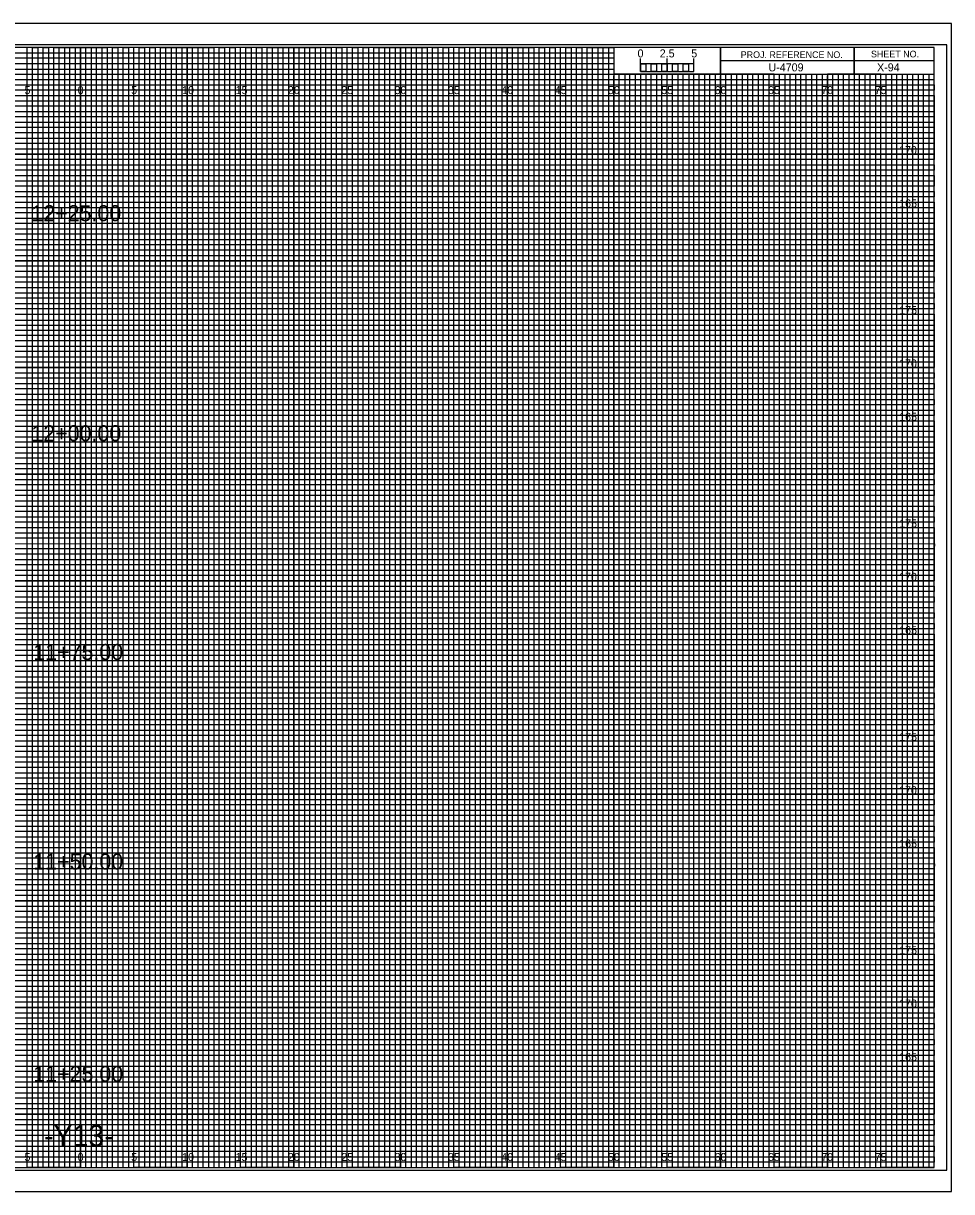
# Model space of a CAD drawing. Extents: x -7 to 162, y 108 to 217.
# Drawn here: x 74.6 to 161.7, y 107.7 to 217.2 of the extents above; entities that cross this region are included whole.
import ezdxf

# ---------------------------------------------------------------- set-up
doc = ezdxf.new("R2010")
doc.units = 0
for name, color, linetype in [('Exist Cross Section Cell', 7, 'Continuous'), ('Exist XS Center Line Elevation Label', 7, 'Continuous'), ('Exist XS Ground Line', 7, 'Continuous'), ('Prop CMT Conc Surface', 7, 'Continuous'), ('Prop CMT Concrete Structures', 7, 'Continuous'), ('Prop CMT Pvmt Course 1', 7, 'Continuous'), ('Prop CMT Pvmt Course 1 CG', 7, 'Continuous'), ('Prop CMT Pvmt Course 2', 7, 'Continuous'), ('Prop CMT Pvmt Course 3', 7, 'Continuous'), ('Prop CMT Pvmt Surface', 7, 'Continuous'), ('Prop CMT Slope Grass', 7, 'Continuous'), ('Prop CMT Subgrade Earthwork', 7, 'Continuous'), ('Prop XS Finish Grade CurbGutter', 7, 'Continuous'), ('Prop XS Hydro Elevations', 7, 'Continuous'), ('Prop XS SE Text', 7, 'Continuous'), ('Prop XS Side Slope Text', 7, 'Continuous'), ('Scratch_Level_0', 7, 'Continuous')]:
    doc.layers.add(name, color=color, linetype=linetype)

msp = doc.modelspace()

# ---------------------------------------------------------------- linework, layer by layer
at = {"layer": 'Exist XS Center Line Elevation Label'}
for points in [[(72.5, 110), (77.5, 110), (77.5, 215), (82.5, 215), (82.5, 110), (87.5, 110), (87.5, 215), (92.5, 215), (92.5, 110), (97.5, 110), (97.5, 215), (102.5, 215), (102.5, 110), (107.5, 110), (107.5, 215), (112.5, 215), (112.5, 110), (117.5, 110), (117.5, 215), (122.5, 215), (122.5, 110), (127.5, 110), (127.5, 215), (129.97, 215), (130, 215), (130, 212.5), (132.5, 212.5), (132.5, 110), (137.5, 110), (137.5, 212.5), (142.5, 212.5), (142.5, 110), (147.5, 110), (147.5, 212.5), (152.5, 212.5), (152.5, 110), (157.5, 110), (157.5, 212.5)], [(0, 212.5), (137.5, 212.5)], [(0, 202.5), (160, 202.5), (160, 207.5), (0, 207.5)], [(0, 192.5), (160, 192.5), (160, 197.5), (0, 197.5)], [(0, 182.5), (160, 182.5), (160, 187.5), (0, 187.5)], [(0, 172.5), (160, 172.5), (160, 177.5), (0, 177.5)], [(0, 162.5), (160, 162.5), (160, 167.5), (0, 167.5)], [(0, 152.5), (160, 152.5), (160, 157.5), (0, 157.5)], [(0, 142.5), (160, 142.5), (160, 147.5), (0, 147.5)], [(0, 132.5), (160, 132.5), (160, 137.5), (0, 137.5)], [(0, 122.5), (160, 122.5), (160, 127.5), (0, 127.5)], [(0, 112.5), (160, 112.5), (160, 117.5), (0, 117.5)]]:
    msp.add_lwpolyline(points, dxfattribs=at)
at = {"layer": 'Exist XS Ground Line'}
for p, q in [((75, 215), (70, 215)), ((75, 110), (75, 215)), ((85, 215), (80, 215)), ((80, 215), (80, 110)), ((85, 110), (85, 215)), ((95, 215), (90, 215)), ((90, 215), (90, 110)), ((95, 110), (95, 215)), ((105, 215), (100, 215)), ((100, 215), (100, 110)), ((105, 110), (105, 215)), ((115, 215), (110, 215)), ((110, 215), (110, 110)), ((115, 110), (115, 215)), ((125, 215), (120, 215)), ((120, 215), (120, 110)), ((125, 110), (125, 215)), ((130, 215), (130, 110)), ((135, 110), (135, 212.5)), ((145, 212.5), (140, 212.5)), ((140, 212.5), (140, 110)), ((145, 110), (145, 212.5)), ((155, 212.5), (150, 212.5)), ((150, 212.5), (150, 110)), ((155, 110), (155, 212.5)), ((80, 110), (75, 110)), ((90, 110), (85, 110)), ((100, 110), (95, 110)), ((110, 110), (105, 110)), ((120, 110), (115, 110)), ((130, 110), (125, 110)), ((140, 110), (135, 110)), ((150, 110), (145, 110)), ((160, 110), (155, 110)), ((160, 110), (160, 110))]:
    msp.add_line(p, q, dxfattribs=at)
for points in [[(0, 210), (160, 210), (160, 205), (0, 205)], [(0, 200), (160, 200), (160, 195), (0, 195)], [(0, 190), (160, 190), (160, 185), (0, 185)], [(0, 180), (160, 180), (160, 175), (0, 175)], [(0, 170), (160, 170), (160, 165), (0, 165)], [(0, 160), (160, 160), (160, 155), (0, 155)], [(0, 150), (160, 150), (160, 145), (0, 145)], [(0, 140), (160, 140), (160, 135), (0, 135)], [(0, 130), (160, 130), (160, 125), (0, 125)], [(0, 120), (160, 120), (160, 115), (0, 115)]]:
    msp.add_lwpolyline(points, dxfattribs=at)
at = {"layer": 'Prop CMT Conc Surface'}
for p, q in [((75, 110), (75, 215)), ((80, 110), (80, 215)), ((85, 110), (85, 215)), ((90, 110), (90, 215)), ((95, 110), (95, 215)), ((100, 110), (100, 215)), ((105, 110), (105, 215)), ((110, 110), (110, 215)), ((115, 110), (115, 215)), ((120, 110), (120, 215)), ((125, 110), (125, 215)), ((130, 110), (130, 212.34)), ((135, 110), (135, 212.34)), ((140, 110), (140, 212.34)), ((145, 110), (145, 212.34)), ((150, 110), (150, 212.34)), ((155, 110), (155, 212.34)), ((0, 210), (160, 210)), ((0, 205), (160, 205)), ((0, 200), (160, 200)), ((0, 195), (160, 195)), ((0, 190), (160, 190)), ((0, 185), (160, 185)), ((0, 180), (160, 180)), ((0, 175), (160, 175)), ((0, 170), (160, 170)), ((0, 165), (160, 165)), ((0, 160), (160, 160)), ((0, 155), (160, 155)), ((0, 150), (160, 150)), ((0, 145), (160, 145)), ((0, 140), (160, 140)), ((0, 135), (160, 135)), ((0, 130), (160, 130)), ((0, 125), (160, 125)), ((0, 120), (160, 120)), ((0, 115), (160, 115))]:
    msp.add_line(p, q, dxfattribs=at)
at = {"layer": 'Prop CMT Pvmt Course 1'}
for p, q in [((133.5, 212.5), (133, 212.5)), ((133, 212.5), (133, 110)), ((133.5, 110), (133.5, 212.5)), ((134.5, 212.5), (134, 212.5)), ((134, 212.5), (134, 110)), ((134.5, 110), (134.5, 212.5)), ((133, 110), (132.5, 110)), ((134, 110), (133.5, 110))]:
    msp.add_line(p, q, dxfattribs=at)
for points in [[(75, 110), (75.5, 110), (75.5, 215), (76, 215), (76, 110)], [(76, 110), (76.5, 110), (76.5, 215), (77, 215), (77, 110)], [(77.5, 110), (78, 110), (78, 215), (78.5, 215), (78.5, 110)], [(78.5, 110), (79, 110), (79, 215), (79.5, 215), (79.5, 110)], [(80, 110), (80.5, 110), (80.5, 215), (81, 215), (81, 110)], [(81, 110), (81.5, 110), (81.5, 215), (82, 215), (82, 110)], [(82.5, 110), (83, 110), (83, 215), (83.5, 215), (83.5, 110)], [(83.5, 110), (84, 110), (84, 215), (84.5, 215), (84.5, 110)], [(85, 110), (85.5, 110), (85.5, 215), (86, 215), (86, 110)], [(86, 110), (86.5, 110), (86.5, 215), (87, 215), (87, 110)], [(87.5, 110), (88, 110), (88, 215), (88.5, 215), (88.5, 110)], [(88.5, 110), (89, 110), (89, 215), (89.5, 215), (89.5, 110)], [(90, 110), (90.5, 110), (90.5, 215), (91, 215), (91, 110)], [(91, 110), (91.5, 110), (91.5, 215), (92, 215), (92, 110)], [(92.5, 110), (93, 110), (93, 215), (93.5, 215), (93.5, 110)], [(93.5, 110), (94, 110), (94, 215), (94.5, 215), (94.5, 110)], [(95, 110), (95.5, 110), (95.5, 215), (96, 215), (96, 110)], [(96, 110), (96.5, 110), (96.5, 215), (97, 215), (97, 110)], [(97.5, 110), (98, 110), (98, 215), (98.5, 215), (98.5, 110)], [(98.5, 110), (99, 110), (99, 215), (99.5, 215), (99.5, 110)], [(100, 110), (100.5, 110), (100.5, 215), (101, 215), (101, 110)], [(101, 110), (101.5, 110), (101.5, 215), (102, 215), (102, 110)], [(102.5, 110), (103, 110), (103, 215), (103.5, 215), (103.5, 110)], [(103.5, 110), (104, 110), (104, 215), (104.5, 215), (104.5, 110)], [(105, 110), (105.5, 110), (105.5, 215), (106, 215), (106, 110)], [(106, 110), (106.5, 110), (106.5, 215), (107, 215), (107, 110)], [(107.5, 110), (108, 110), (108, 215), (108.5, 215), (108.5, 110)], [(108.5, 110), (109, 110), (109, 215), (109.5, 215), (109.5, 110)], [(110, 110), (110.5, 110), (110.5, 215), (111, 215), (111, 110)], [(111, 110), (111.5, 110), (111.5, 215), (112, 215), (112, 110)], [(112.5, 110), (113, 110), (113, 215), (113.5, 215), (113.5, 110)], [(113.5, 110), (114, 110), (114, 215), (114.5, 215), (114.5, 110)], [(115, 110), (115.5, 110), (115.5, 215), (116, 215), (116, 110)], [(116, 110), (116.5, 110), (116.5, 215), (117, 215), (117, 110)], [(117.5, 110), (118, 110), (118, 215), (118.5, 215), (118.5, 110)], [(118.5, 110), (119, 110), (119, 215), (119.5, 215), (119.5, 110)], [(120, 110), (120.5, 110), (120.5, 215), (121, 215), (121, 110)], [(121, 110), (121.5, 110), (121.5, 215), (122, 215), (122, 110)], [(122.5, 110), (123, 110), (123, 215), (123.5, 215), (123.5, 110)], [(123.5, 110), (124, 110), (124, 215), (124.5, 215), (124.5, 110)], [(125, 110), (125.5, 110), (125.5, 215), (126, 215), (126, 110)], [(126, 110), (126.5, 110), (126.5, 215), (127, 215), (127, 110)], [(127.5, 110), (128, 110), (128, 215), (128.5, 215), (128.5, 110)], [(128.5, 110), (129, 110), (129, 215), (129.5, 215), (129.5, 110)], [(130, 110), (130.5, 110), (130.5, 212.5), (131.01, 212.5), (131.01, 110)], [(131, 110), (131.5, 110), (131.5, 212.5), (132, 212.5), (132, 110)], [(135, 110), (135.49, 110), (135.49, 212.5), (136, 212.5), (136, 110)], [(136, 110), (136.5, 110), (136.5, 212.5), (137.03, 212.5), (137.03, 110)], [(137.5, 110), (138, 110), (138, 212.5), (138.5, 212.5), (138.5, 110)], [(138.5, 110), (139, 110), (139, 212.5), (139.5, 212.5), (139.5, 110)], [(140, 110), (140.5, 110), (140.5, 212.5), (141, 212.5), (141, 110)], [(141, 110), (141.5, 110), (141.5, 212.5), (142, 212.5), (142, 110)], [(142.5, 110), (143, 110), (143, 212.5), (143.5, 212.5), (143.5, 110)], [(143.5, 110), (144, 110), (144, 212.5), (144.5, 212.5), (144.5, 110)], [(145, 110), (145.5, 110), (145.5, 212.5), (146, 212.5), (146, 110)], [(146, 110), (146.5, 110), (146.5, 212.5), (147, 212.5), (147, 110)], [(147.5, 110), (148, 110), (148, 212.5), (148.5, 212.5), (148.5, 110)], [(148.5, 110), (149, 110), (149, 212.5), (149.5, 212.5), (149.5, 110)], [(150, 110), (150.5, 110), (150.5, 212.5), (151, 212.5), (151, 110)], [(151, 110), (151.5, 110), (151.5, 212.5), (152, 212.5), (152, 110)], [(152.5, 110), (153, 110), (153, 212.5), (153.5, 212.5), (153.5, 110)], [(153.5, 110), (154, 110), (154, 212.5), (154.5, 212.5), (154.5, 110)], [(155, 110), (155.5, 110), (155.5, 212.5), (156, 212.5), (156, 110)], [(156, 110), (156.5, 110), (156.5, 212.5), (157, 212.5), (157, 110)], [(157.5, 110), (158, 110), (158, 212.5), (158.5, 212.5), (158.5, 110)], [(158.5, 110), (159, 110), (159, 212.5), (159.5, 212.5), (159.5, 110)]]:
    msp.add_lwpolyline(points, dxfattribs=at)
at = {"layer": 'Prop CMT Pvmt Course 1 CG'}
for p, q in [((132.5, 212.75), (132.5, 213.95)), ((132.5, 213.45), (132.5, 213.95)), ((135, 212.75), (135, 213.95)), ((137.5, 212.75), (137.5, 213.95)), ((137.5, 213.45), (137.5, 213.95))]:
    msp.add_line(p, q, dxfattribs=at)
for points in [[(137.5, 213.45), (132.5, 213.45), (132.5, 212.75), (137.5, 212.75)], [(132.5, 213.45), (133, 213.45), (133, 212.75), (132.5, 212.75)], [(133.5, 213.45), (134, 213.45), (134, 212.75), (133.5, 212.75)], [(134.5, 213.45), (135, 213.45), (135, 212.75), (134.5, 212.75)], [(135.5, 213.45), (136, 213.45), (136, 212.75), (135.5, 212.75)], [(136.5, 213.45), (137, 213.45), (137, 212.75), (136.5, 212.75)]]:
    msp.add_lwpolyline(points, close=True, dxfattribs=at)
at = {"layer": 'Prop CMT Pvmt Course 2'}
msp.add_lwpolyline([(-6.7, 107.75), (161.65, 107.75), (161.65, 217.25), (-6.7, 217.25)], close=True, dxfattribs=at)
at = {"layer": 'Prop CMT Pvmt Course 3'}
msp.add_lwpolyline([(-5.4, 109.75), (161.2, 109.75), (161.2, 215.25), (-5.4, 215.25)], close=True, dxfattribs=at)
at = {"layer": 'Prop CMT Slope Grass'}
for p, q in [((161.65, 217.25), (-6.7, 217.25)), ((-6.7, 107.75), (161.65, 107.75))]:
    msp.add_line(p, q, dxfattribs=at)
at = {"layer": 'Prop CMT Subgrade Earthwork'}
for p, q in [((152.5, 215), (152.5, 212.5)), ((152.5, 212.5), (152.5, 215)), ((160, 213.75), (140, 213.75)), ((140, 213.75), (140, 212.5)), ((140, 212.5), (160, 212.5))]:
    msp.add_line(p, q, dxfattribs=at)
for points in [[(160, 215), (0, 215), (0, 110), (160, 110)], [(140, 215), (130, 215), (130, 212.52), (140, 212.52)], [(160, 215), (140, 215), (140, 212.5), (160, 212.5)]]:
    msp.add_lwpolyline(points, close=True, dxfattribs=at)
at = {"layer": 'Scratch_Level_0'}
for p, q in [((0, 214.5), (130, 214.5)), ((130, 213.99), (0, 213.99)), ((130, 214.5), (130, 213.99)), ((0, 213.5), (130, 213.5)), ((130, 212.94), (0, 212.94)), ((130, 213.5), (130, 212.94)), ((0, 212), (160, 212))]:
    msp.add_line(p, q, dxfattribs=at)
for points in [[(0, 211.5), (135, 211.5), (160, 211.5), (160, 211), (0, 211)], [(0, 210.5), (160, 210.5), (160, 209.5), (0, 209.5)], [(0, 209), (160, 209), (160, 208.5), (0, 208.49)], [(0, 208), (160, 208), (160, 207), (0, 207)], [(0, 206.5), (160, 206.5), (160, 206), (0, 206)], [(0, 205.5), (160, 205.5), (160, 204.5), (0, 204.5)], [(0, 204), (160, 204), (160, 203.5), (0, 203.5)], [(0, 203), (160, 203), (160, 202), (0, 202)], [(0, 201.5), (160, 201.5), (160, 201), (0, 201)], [(0, 200.5), (160, 200.5), (160, 199.5), (0, 199.5)], [(0, 199), (160, 199), (160, 198.5), (0, 198.5)], [(0, 198), (160, 198), (160, 196.97), (160, 196.5), (160, 196), (0, 196)], [(0, 197), (160, 197), (160, 196.5), (0, 196.5)], [(0, 195.5), (160, 195.5), (160, 194.5), (0, 194.52)], [(0, 194.52), (160, 194.5), (160, 194), (0, 194)], [(0, 193.5), (160, 193.5), (160, 193), (0, 193)], [(0, 192), (160, 192), (160, 191.5), (0, 191.5)], [(0, 191), (160, 191), (160, 190.5), (0, 190.5)], [(-0.04, 189.44), (160, 189.44), (160, 188.94), (-0.04, 188.94)], [(0, 188.5), (160, 188.5), (160, 188), (0, 188)], [(0, 187), (160, 187), (160, 186.5), (0, 186.5)], [(0, 186), (160, 186), (160, 185.5), (0, 185.5)], [(0, 184.5), (160, 184.5), (160, 184), (0, 184)], [(0, 183.5), (160, 183.5), (160, 183), (0, 183)], [(0, 182), (160, 182), (160, 181.5), (0, 181.5)], [(0, 181), (160, 181), (160, 180.5), (0, 180.5)], [(0, 179.5), (160, 179.5), (160, 178.99), (0, 179)], [(0, 178.5), (160, 178.5), (160, 178), (0, 178)], [(0, 177), (160, 177), (160, 176.5), (0, 176.5)], [(0, 176), (160, 176), (160, 175.5), (0, 175.5)], [(0, 174.5), (160, 174.5), (160, 174), (0, 174)], [(0, 173.5), (160, 173.5), (160, 173), (0, 173)], [(0, 172), (160, 172), (160, 171.5), (0, 171.5)], [(0, 171), (160, 171), (160, 170.5), (0, 170.5)], [(0, 169.5), (160, 169.5), (160, 169), (0, 169)], [(0, 168.5), (160.03, 168.46), (160, 168), (0, 168)], [(0, 167), (160, 167), (160, 166.5), (0, 166.5)], [(0, 166), (160, 166), (160, 165.5), (0, 165.5)], [(0, 164.5), (160, 164.5), (160, 164), (0, 164)], [(0, 163.5), (160, 163.5), (160, 163), (0, 163)], [(0, 162), (160, 162), (160, 161.5), (0, 161.5)], [(0, 161), (160, 161), (160, 160.5), (0, 160.5)], [(0, 159.5), (160, 159.5), (160, 159), (0, 159)], [(0, 158.5), (160, 158.5), (160, 158), (0, 158)], [(0, 157), (160, 157), (160, 156.5), (0, 156.5)], [(0, 156), (160, 156), (160, 155.5), (0, 155.5)], [(0, 154.5), (160, 154.5), (160, 154), (0, 154)], [(0, 153.5), (160, 153.5), (160, 153), (0, 153)], [(0, 152), (160, 152), (160, 151.5), (0, 151.5)], [(0, 151), (160, 151), (160, 150.5), (0, 150.5)], [(0, 149.5), (160, 149.5), (160, 148.99), (0, 149)], [(0, 148.5), (160, 148.5), (160, 148), (0, 148)], [(0, 147), (160, 147), (160, 146.5), (0, 146.5)], [(0, 146), (160, 146), (160, 145.5), (0, 145.5)], [(0, 144.5), (160, 144.5), (160, 144), (0, 144)], [(0, 143.5), (160, 143.5), (160, 143), (0, 143)], [(0, 142), (160, 142), (160, 141.5), (0, 141.5)], [(0, 141), (160, 141), (160, 140.5), (0, 140.5)], [(0, 139.5), (160, 139.5), (160, 139), (0, 139)], [(0, 138.5), (160.03, 138.46), (160, 138), (0, 138)], [(0, 137), (160, 137), (160, 136.5), (0, 136.5)], [(0, 136), (160, 136), (160, 135.5), (0, 135.5)], [(0, 134.5), (160, 134.5), (160, 134), (0, 134)], [(0, 133.5), (160, 133.5), (160, 133), (0, 133)], [(0, 132), (160, 132), (160, 131.5), (0, 131.5)], [(0, 131), (160, 131), (160, 130.5), (0, 130.5)], [(0, 129.5), (160, 129.5), (160, 129), (0, 129)], [(0, 128.5), (160, 128.5), (160, 128), (0, 128)], [(0, 127), (160, 127), (160, 126.5), (0, 126.5)], [(0, 126), (160, 126), (160, 125.5), (0, 125.5)], [(0, 124.5), (160, 124.5), (160, 124), (0, 124)], [(0, 123.5), (160, 123.5), (160, 123), (0, 123)], [(0, 122), (160, 122), (160, 121.5), (0, 121.5)], [(0, 121), (160, 121), (160, 120.5), (0, 120.5)], [(0, 119.5), (160, 119.5), (160, 119), (0, 119)], [(0, 118.5), (160, 118.5), (160, 118), (0, 118)], [(0, 117), (160, 117), (160, 116.5), (0, 116.5)], [(0, 116), (160, 116), (160, 115.5), (0, 115.5)], [(0, 114.5), (160, 114.5), (160, 114), (0, 114)], [(0, 113.5), (160, 113.5), (160, 113), (0, 113)], [(0, 112), (160, 112), (160, 111.5), (0, 111.5)], [(0, 111), (160, 111), (160, 110.5), (0, 110.5)]]:
    msp.add_lwpolyline(points, dxfattribs=at)

# ---------------------------------------------------------------- texts
at = {"layer": 'Exist Cross Section Cell'}
for s, p in [('5', (74.74, 210.62)), ('0', (79.73, 210.62)), ('0', (79.73, 210.62)), ('5', (84.74, 210.62)), ('10', (89.52, 210.62)), ('15', (94.53, 210.62)), ('20', (99.43, 210.62)), ('25', (104.44, 210.62)), ('30', (109.43, 210.62)), ('35', (114.44, 210.62)), ('40', (119.43, 210.62)), ('45', (124.44, 210.62)), ('50', (129.43, 210.62)), ('55', (134.44, 210.62)), ('60', (139.43, 210.62)), ('65', (144.44, 210.62)), ('70', (149.43, 210.62)), ('75', (154.44, 210.62)), ('5', (74.74, 110.62)), ('0', (79.73, 110.62)), ('0', (79.73, 110.62)), ('5', (84.74, 110.62)), ('10', (89.52, 110.62)), ('15', (94.53, 110.62)), ('20', (99.43, 110.62)), ('25', (104.44, 110.62)), ('30', (109.43, 110.62)), ('35', (114.44, 110.62)), ('40', (119.43, 110.62)), ('45', (124.44, 110.62)), ('50', (129.43, 110.62)), ('55', (134.44, 110.62)), ('60', (139.43, 110.62)), ('65', (144.44, 110.62)), ('70', (149.43, 110.62)), ('75', (154.44, 110.62))]:
    msp.add_text(s, height=0.75, dxfattribs=at).set_placement(p)
at = {"layer": 'Prop CMT Concrete Structures'}
for s, p in [('170', (156.72, 205)), ('165', (156.73, 200)), ('175', (156.73, 190)), ('170', (156.72, 185)), ('165', (156.73, 180)), ('175', (156.73, 170)), ('170', (156.72, 165)), ('165', (156.73, 160)), ('175', (156.73, 150)), ('170', (156.72, 145)), ('165', (156.73, 140)), ('175', (156.73, 130)), ('170', (156.72, 125)), ('165', (156.73, 120))]:
    msp.add_text(s, height=0.75, dxfattribs=at).set_placement(p)
at = {"layer": 'Prop CMT Pvmt Course 1 CG'}
msp.add_text('0', height=0.75, dxfattribs=at).set_placement((132.21, 214.06))
at = {"layer": 'Prop CMT Pvmt Surface'}
for s, p in [('12+25.00', (75.39, 198.71)), ('12+00.00', (75.39, 178.08)), ('11+75.00', (75.57, 157.58)), ('11+50.00', (75.57, 137.94)), ('11+25.00', (75.57, 118.04))]:
    msp.add_text(s, height=1.5, dxfattribs=at).set_placement(p)
at = {"layer": 'Prop CMT Subgrade Earthwork'}
for s, p in [('PROJ. REFERENCE NO.', (141.88, 214)), ('SHEET NO.', (154.09, 214.06))]:
    msp.add_text(s, height=0.625, dxfattribs=at).set_placement(p)
at = {"layer": 'Prop XS Finish Grade CurbGutter'}
for s, p in [('2.5', (134.29, 214.06)), ('5', (137.24, 214.06))]:
    msp.add_text(s, height=0.75, dxfattribs=at).set_placement(p)
at = {"layer": 'Prop XS Hydro Elevations'}
msp.add_text('-Y13-', height=2, dxfattribs=at).set_placement((76.57, 112))
at = {"layer": 'Prop XS SE Text'}
msp.add_text('U-4709', height=0.75, dxfattribs=at).set_placement((144.48, 212.75))
at = {"layer": 'Prop XS Side Slope Text'}
msp.add_text('X-94', height=0.75, dxfattribs=at).set_placement((154.66, 212.75))

doc.saveas('drawing.dxf')
